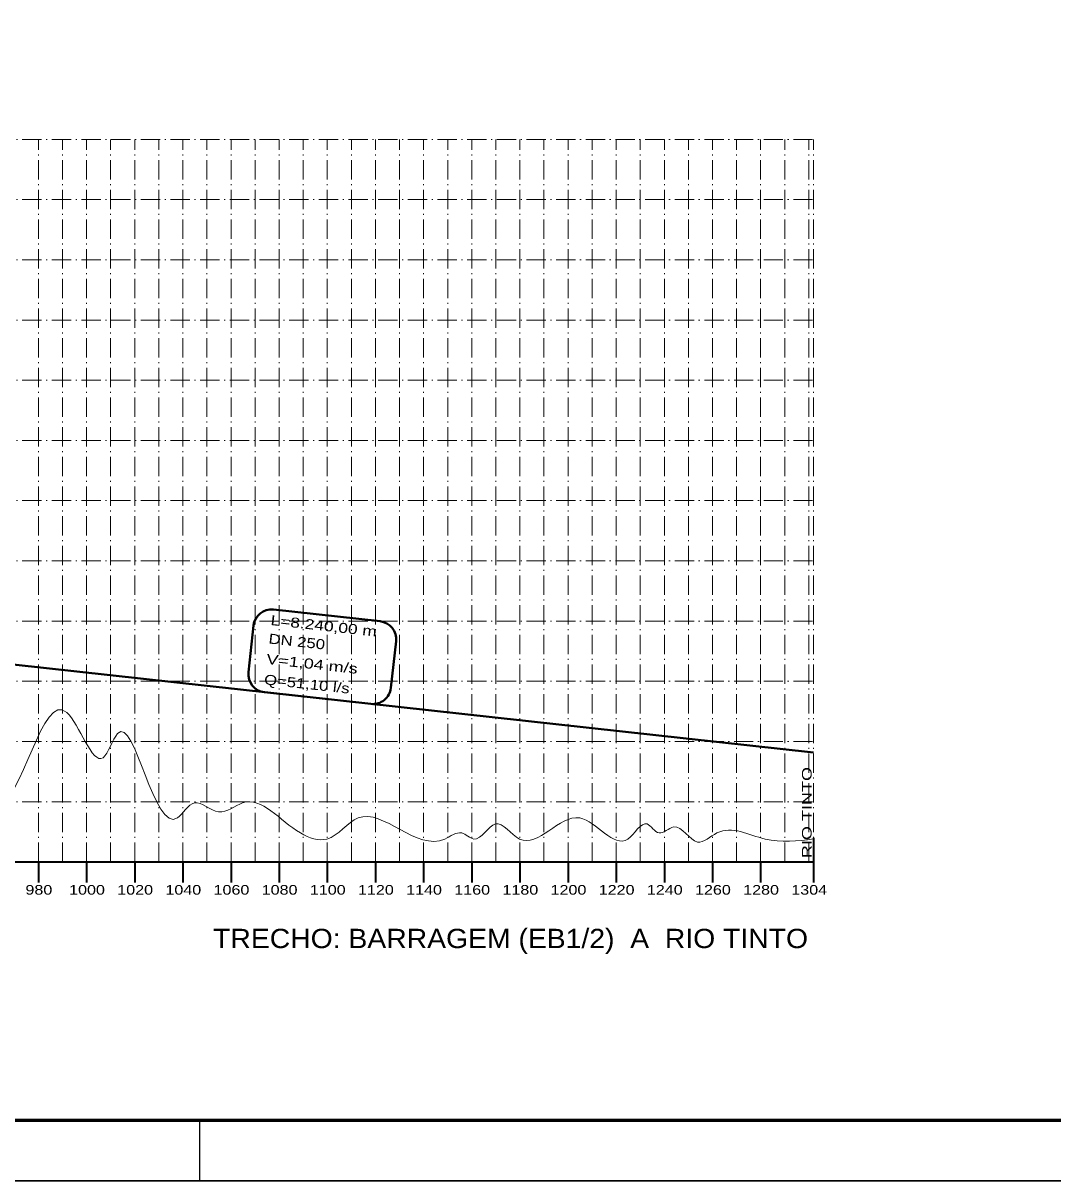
# Model space of a CAD drawing. Extents: x -4 to 42046, y -3 to 29697.
# Drawn here: x 22579 to 31133, y -3 to 9612 of the extents above; entities that cross this region are included whole.
import ezdxf
from ezdxf.enums import TextEntityAlignment as Align

# ---------------------------------------------------------------- set-up
doc = ezdxf.new("R2010")
doc.units = 0
doc.header["$LTSCALE"] = 32
doc.linetypes.add('DOT_DASHED', pattern=[7.7, 5, -1.2, 0.3, -1.2])
for name, color, linetype, lineweight in [('1', 7, 'DOT_DASHED', 13), ('24', 7, 'Continuous', 35), ('56', 7, 'Continuous', 13), ('62', 7, 'Continuous', 13), ('63', 7, 'Continuous', 25), ('9', 7, 'Continuous', 40)]:
    doc.layers.add(name, color=color, linetype=linetype, lineweight=lineweight)

msp = doc.modelspace()

# ---------------------------------------------------------------- linework, layer by layer
at = {"layer": '1'}
for p, q in [((3105.77, 8646.17), (29145.77, 8646.17)), ((22705.77, 2646.17), (22705.77, 8646.17)), ((22905.77, 2646.17), (22905.77, 8646.17)), ((23105.77, 2646.17), (23105.77, 8646.17)), ((23305.77, 2646.17), (23305.77, 8646.17)), ((23505.77, 2646.17), (23505.77, 8646.17)), ((23705.77, 2646.17), (23705.77, 8646.17)), ((23905.77, 2646.17), (23905.77, 8646.17)), ((24105.77, 2646.17), (24105.77, 8646.17)), ((24305.77, 2646.17), (24305.77, 8646.17)), ((24505.77, 2646.17), (24505.77, 8646.17)), ((24705.77, 2646.17), (24705.77, 8646.17)), ((24905.77, 2646.17), (24905.77, 8646.17)), ((25105.77, 2646.17), (25105.77, 8646.17)), ((25305.77, 2646.17), (25305.77, 8646.17)), ((25505.77, 2646.17), (25505.77, 8646.17)), ((25705.77, 2646.17), (25705.77, 8646.17)), ((25905.77, 2646.17), (25905.77, 8646.17)), ((26105.77, 2646.17), (26105.77, 8646.17)), ((26305.77, 2646.17), (26305.77, 8646.17)), ((26505.77, 2646.17), (26505.77, 8646.17)), ((26705.77, 2646.17), (26705.77, 8646.17)), ((26905.77, 2646.17), (26905.77, 8646.17)), ((27105.77, 2646.17), (27105.77, 8646.17)), ((27305.77, 2646.17), (27305.77, 8646.17)), ((27505.77, 2646.17), (27505.77, 8646.17)), ((27705.77, 2646.17), (27705.77, 8646.17)), ((27905.77, 2646.17), (27905.77, 8646.17)), ((28105.77, 2646.17), (28105.77, 8646.17)), ((28305.77, 2646.17), (28305.77, 8646.17)), ((28505.77, 2646.17), (28505.77, 8646.17)), ((28705.77, 2646.17), (28705.77, 8646.17)), ((28905.77, 2646.17), (28905.77, 8646.17)), ((29105.77, 2646.17), (29105.77, 8646.17)), ((29145.77, 2646.17), (29145.77, 8646.17)), ((3105.77, 8146.17), (29145.77, 8146.17)), ((3105.77, 7646.17), (29145.77, 7646.17)), ((3105.77, 7146.17), (29145.77, 7146.17)), ((3105.77, 6646.17), (29145.77, 6646.17)), ((3105.77, 6146.17), (29145.77, 6146.17)), ((3105.77, 5646.17), (29145.77, 5646.17)), ((3105.77, 5146.17), (29145.77, 5146.17)), ((3105.77, 4646.17), (29145.77, 4646.17)), ((3105.77, 4146.17), (29145.77, 4146.17)), ((3105.77, 3646.17), (29145.77, 3646.17)), ((3105.77, 3146.17), (29145.77, 3146.17))]:
    msp.add_line(p, q, dxfattribs=at)
at = {"layer": '56'}
msp.add_spline([(3442.18, 3641.64), (3562.37, 3886.04), (3682.37, 4136.04), (3802.37, 4461.04), (3902.37, 4136.04), (3962.37, 3761.04), (4222.37, 4586.04), (4922.37, 4261.04), (5542.37, 4386.04), (5622.37, 4336.04), (5722.37, 4386.04), (5822.37, 4461.04), (6022.37, 4286.04), (6222.37, 4361.04), (6522.37, 4261.04), (6922.37, 4386.04), (7322.37, 4086.04), (7642.37, 4636.04), (7742.37, 4761.04), (8062.37, 4336.04), (8442.37, 4636.04), (8702.37, 4561.04), (9002.37, 4636.04), (9202.37, 4386.04), (9442.37, 4711.04), (9642.37, 4486.04), (9902.37, 4886.04), (10422.37, 4636.04), (10882.37, 4936.04), (11642.37, 4261.04), (11942.37, 4511.04), (12062.37, 4386.04), (12382.37, 4411.04), (12982.37, 3611.04), (13192.37, 3711.04), (13592.37, 3636.04), (14032.37, 4011.04), (14532.37, 4661.04), (14732.37, 4386.04), (15932.37, 3461.04), (16672.37, 4386.04), (17705.77, 4596.17), (19279.94, 4205.37), (19682.37, 3586.04), (19842.37, 3761.04), (19942.37, 3836.04), (20242.37, 3636.04), (20442.37, 3786.04), (20542.37, 3636.04), (20942.37, 3636.04), (21942.37, 3386.04), (22342.37, 3086.04), (22942.37, 3886.04), (23242.37, 3511.04), (23362.37, 3711.04), (23862.37, 3011.04), (24002.37, 3136.04), (24202.37, 3061.04), (24402.37, 3136.04), (24882.37, 2886.04), (25102.37, 2836.04), (25362.37, 3011.04), (26082.37, 2836.04), (26222.37, 2886.04), (26322.37, 2836.04), (26502.37, 2961.04), (26702.37, 2836.04), (27202.37, 3011.04), (27602.37, 2836.04), (27762.37, 2961.04), (27862.37, 2886.04), (27982.37, 2936.04), (28182.37, 2811.04), (28342.37, 2886.04), (28742.37, 2836.04), (29145.65, 2836.26)], degree=3, dxfattribs=at)
at = {"layer": '62', "lineweight": 35}
for p, q in [((29145.8, 2846.36), (29145.8, 2646.36)), ((3105.77, 2646.17), (29145.77, 2646.17)), ((22705.77, 2646.17), (22705.77, 2475.48)), ((23105.77, 2646.17), (23105.77, 2475.48)), ((23505.77, 2646.17), (23505.77, 2475.48)), ((23905.77, 2646.17), (23905.77, 2475.48)), ((24305.77, 2646.17), (24305.77, 2475.48)), ((24705.77, 2646.17), (24705.77, 2475.48)), ((25105.77, 2646.17), (25105.77, 2475.48)), ((25505.77, 2646.17), (25505.77, 2475.48)), ((25905.77, 2646.17), (25905.77, 2475.48)), ((26305.77, 2646.17), (26305.77, 2475.48)), ((26705.77, 2646.17), (26705.77, 2475.48)), ((27105.77, 2646.17), (27105.77, 2475.48)), ((27505.77, 2646.17), (27505.77, 2475.48)), ((27905.77, 2646.17), (27905.77, 2475.48)), ((28305.77, 2646.17), (28305.77, 2475.48)), ((28705.77, 2646.17), (28705.77, 2475.48)), ((29145.77, 2646.17), (29145.77, 2475.48))]:
    msp.add_line(p, q, dxfattribs=at)
at = {"layer": '63', "lineweight": 60}
msp.add_line((41545.8, 497.03), (1245.8, 497.03), dxfattribs=at)
at = {"layer": '63'}
msp.add_line((24045.8, -2.97), (24045.8, 497.03), dxfattribs=at)
for points in [[(-4.21, -2.97), (42045.8, -2.97), (42045.8, 29697.03)], [(-4.21, -2.97), (42045.8, -2.97), (-4.21, -2.97)]]:
    msp.add_lwpolyline(points, dxfattribs=at)
at = {"layer": '63', "lineweight": 60}
msp.add_lwpolyline([(23554.57, 497.03), (1245.8, 497.03), (1245.8, 29197.03)], dxfattribs=at)
at = {"layer": '9'}
for p, q in [((24658.37, 4741.35), (25543.89, 4644.09)), ((24492.89, 4608.62), (24450.28, 4220.69)), ((25676.62, 4478.61), (25634.01, 4090.68)), ((24583.01, 4055.21), (25468.53, 3957.96))]:
    msp.add_line(p, q, dxfattribs=at)
msp.add_lwpolyline([(3105.77, 6140.34), (4205.77, 5946.84), (6905.77, 5656.59), (17705.77, 4721.17), (19305.77, 4582.59), (20905.77, 4459.09), (29145.77, 3554.09)], dxfattribs=at)
for centre, start, end in [((24641.99, 4592.25), 83.73232, 173.73232), ((25527.52, 4494.99), 353.73232, 83.73232), ((24599.38, 4204.32), 173.73232, 263.73232), ((25484.91, 4107.06), 263.73232, 353.73232)]:
    msp.add_arc(centre, 150, start, end, dxfattribs=at)

# ---------------------------------------------------------------- texts
at = {"layer": '24', "width": 1.4}
msp.add_text('RIO TINTO', height=80, rotation=90, dxfattribs=at).set_placement((29129.24, 2677.07))
at = {"layer": '24'}
for s, height, width, p in [('980', 80, 1.25, (22709.27, 2373.89)), ('1000', 80, 1.25, (23109.27, 2373.89)), ('1020', 80, 1.25, (23509.27, 2373.89)), ('1040', 80, 1.25, (23909.27, 2373.89)), ('1060', 80, 1.25, (24309.27, 2373.89)), ('1080', 80, 1.25, (24709.27, 2373.89)), ('1100', 80, 1.25, (25109.27, 2373.89)), ('1120', 80, 1.25, (25509.27, 2373.89)), ('1140', 80, 1.25, (25909.27, 2373.89)), ('1160', 80, 1.25, (26309.27, 2373.89)), ('1180', 80, 1.25, (26709.27, 2373.89)), ('1200', 80, 1.25, (27109.27, 2373.89)), ('1220', 80, 1.25, (27509.27, 2373.89)), ('1240', 80, 1.25, (27909.27, 2373.89)), ('1260', 80, 1.25, (28309.27, 2373.89)), ('1280', 80, 1.25, (28709.27, 2373.89)), ('1304', 80, 1.25, (29109.27, 2373.89)), ('TRECHO: BARRAGEM (EB1/2)  A  RIO TINTO', 160, 1.1, (26628.26, 1930.04))]:
    msp.add_text(s, height=height, dxfattribs=dict(at, width=width)).set_placement(p, align=Align.CENTER)
at = {"layer": '9'}
for s, width, p in [('L=8.240,00 m', 1.3, (24631.43, 4614.06)), ('DN 250', 1.25, (24614.56, 4460.49)), ('V=1,04 m/s', 1.35, (24595.94, 4290.92)), ('Q=51,10 l/s', 1.25, (24577.31, 4121.35))]:
    msp.add_text(s, height=82.98, rotation=353.732, dxfattribs=dict(at, width=width)).set_placement(p)

doc.saveas('drawing.dxf')
